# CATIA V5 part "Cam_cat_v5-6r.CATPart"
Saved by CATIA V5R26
Part number: Cam
Bounding box of the stored display mesh (mm): x -10 to 60, y -35 to 35, z -50 to 30
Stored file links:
  D:\_Deepak\CATIA\CATIA V5 2015 Parts Files\Tutorial Files\Tutorials\c16_catia_v5_6r2016_tut\Cam Follower mechanism\Cam_cat_v5-6r2012.CATPart
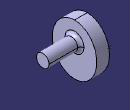
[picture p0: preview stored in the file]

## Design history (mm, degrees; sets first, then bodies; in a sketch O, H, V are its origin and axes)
Body1 (main body)
  Sketch1 on yz-plane, origin (0, 0, 0), H (0, 1, 0), V (0, 0, 1)
    point P1 (0, -10)
    ellipse A1 centre (0, -10) semi-axes 40, 35 rotation 90
    point P2 (0, 30)
    "Radius" A1 = 40
    distance V A1 = 35
    distance P1 H = 10
    coincidence: P1 V, P2 V, A1 P2
  Pad1: profile Sketch1, direction (1, 0, 0), length 10, mirrored extent
  Sketch2 on end face of Pad1, origin (10, 0, 0), H (0, 1, 0), V (0, 0, 1)
    circle A1 centre (0, 0) radius 10
    radius A1 = 10
  Pad2: profile Sketch2, direction (1, 0, 0), length 50
  Sketch3 on start face of Pad1, origin (-10, 0, 0), H (0, -1, 0), V (0, 0, 1)
    point P1 (-33.8886, 0)
    reference projected curve E1 from edge [start face of Pad1 | face of Pad1 from Sketch1.A1]
    coincidence: P1 H, P1 E1
  Fillet1: radius 5, on edge [end face of Pad1 | face of Pad2 from Sketch2.A1]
